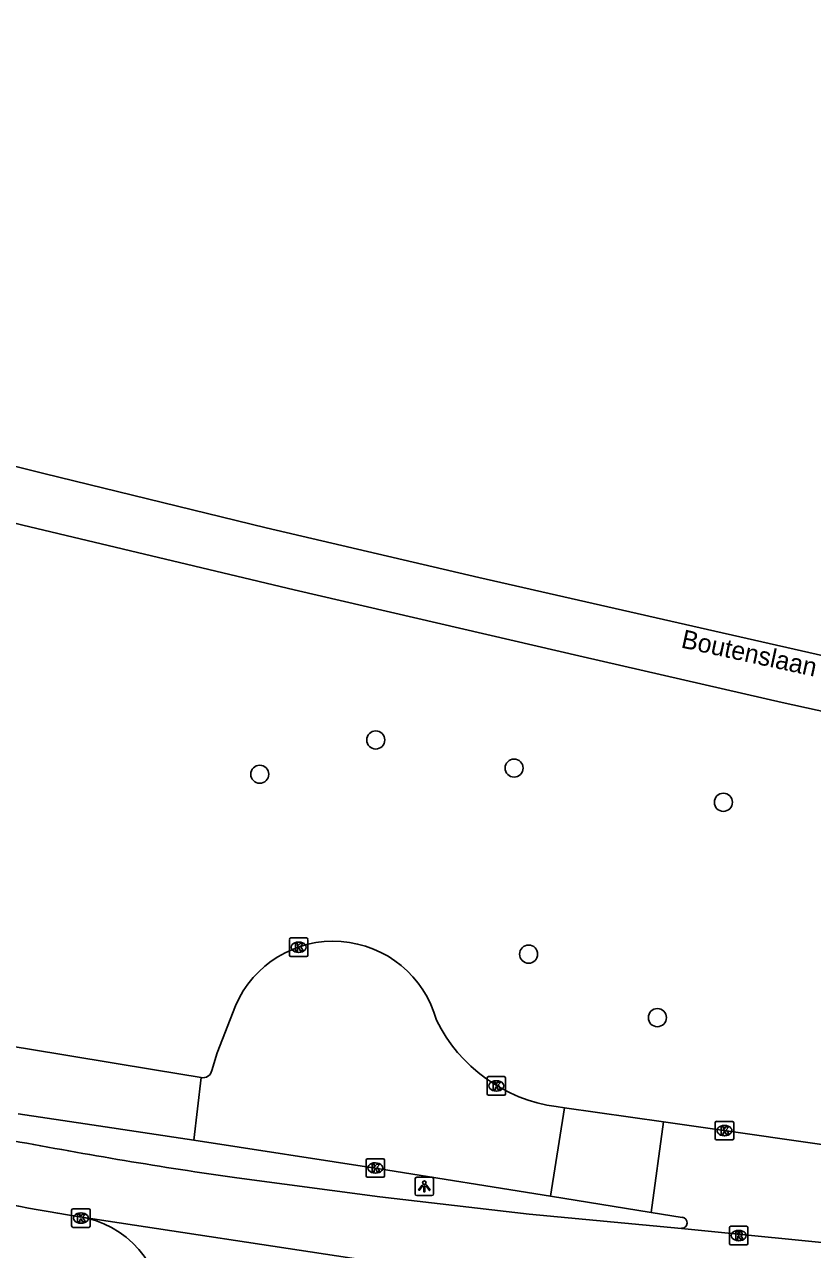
# Model space of a CAD drawing. Extents: x 160203 to 161526, y 379529 to 381797.
# Drawn here: x 161014 to 161056.6, y 381727.7 to 381793.9 of the extents above; entities that cross this region are included whole.
import ezdxf

# ---------------------------------------------------------------- set-up
doc = ezdxf.new("R2010")
doc.units = 0
for name, color, linetype in [('IMGEO_Boom', 7, 'Continuous'), ('IMGEO_Fietspad_gesloten', 7, 'Continuous'), ('IMGEO_Kolk', 7, 'Continuous'), ('IMGEO_Lichtpunt', 7, 'Continuous'), ('IMGEO_Openbare_ruimte_label', 7, 'Continuous'), ('IMGEO_Rijbaan_lokaal_gesloten', 7, 'Continuous'), ('IMGEO_Rijbaan_lokaal_open', 7, 'Continuous'), ('IMGEO_Rijbaan_regionaal_gesloten', 7, 'Continuous'), ('IMGEO_Rioolput', 7, 'Continuous')]:
    doc.layers.add(name, color=color, linetype=linetype)

msp = doc.modelspace()

# ---------------------------------------------------------------- linework, layer by layer
at = {"layer": 'IMGEO_Boom'}
for centre in [(161033.006, 381755.255), (161040.49, 381753.734), (161026.733, 381753.404), (161051.806, 381751.884), (161041.274, 381743.672), (161048.237, 381740.239)]:
    msp.add_circle(centre, 0.489, dxfattribs=at)
at = {"layer": 'IMGEO_Fietspad_gesloten'}
for points in [[(161049.533, 381728.846), (161041.308, 381729.618), (161033.225, 381730.555), (161025.491, 381731.569)], [(161016.874, 381729.484), (161017.118, 381729.447)]]:
    msp.add_lwpolyline(points, dxfattribs=at)
for centre, radius, start, end in [((161067.918, 382023.698), 295.194, 259.35423, 261.73648), ((161079.415, 382097.832), 373.62, 257.72776, 260.3637)]:
    msp.add_arc(centre, radius, start, end, dxfattribs=at)
at = {"layer": 'IMGEO_Kolk'}
for p, q in [((161028.339, 381743.622), (161028.339, 381744.474)), ((161028.414, 381744.548), (161029.266, 381744.548)), ((161028.827, 381744.328), (161028.852, 381744.328)), ((161029.34, 381744.474), (161029.34, 381743.622)), ((161029.266, 381743.548), (161028.414, 381743.548)), ((161028.85, 381743.768), (161028.825, 381743.768)), ((161039.03, 381736.123), (161039.03, 381736.975)), ((161039.105, 381737.049), (161039.957, 381737.049)), ((161040.031, 381736.975), (161040.031, 381736.123)), ((161039.541, 381736.269), (161039.516, 381736.269)), ((161039.518, 381736.829), (161039.543, 381736.829)), ((161039.957, 381736.049), (161039.105, 381736.049)), ((161051.365, 381733.706), (161051.365, 381734.558)), ((161051.44, 381734.632), (161052.292, 381734.632)), ((161051.853, 381734.412), (161051.878, 381734.412)), ((161052.366, 381734.558), (161052.366, 381733.706)), ((161052.292, 381733.632), (161051.44, 381733.632)), ((161051.876, 381733.852), (161051.851, 381733.852)), ((161032.485, 381731.683), (161032.485, 381732.535)), ((161032.56, 381732.609), (161033.412, 381732.609)), ((161032.973, 381732.389), (161032.998, 381732.389)), ((161033.486, 381732.535), (161033.486, 381731.683)), ((161033.412, 381731.609), (161032.56, 381731.609)), ((161032.996, 381731.829), (161032.971, 381731.829)), ((161016.562, 381728.974), (161016.562, 381729.826)), ((161016.637, 381729.9), (161017.489, 381729.9)), ((161017.05, 381729.68), (161017.075, 381729.68)), ((161017.563, 381729.826), (161017.563, 381728.974)), ((161017.073, 381729.12), (161017.048, 381729.12)), ((161017.489, 381728.9), (161016.637, 381728.9))]:
    msp.add_line(p, q, dxfattribs=at)
for points in [[(161028.339, 381743.622), (161028.339, 381744.474)], [(161028.414, 381744.548), (161029.266, 381744.548)], [(161028.66, 381744.248), (161028.783, 381744.248), (161028.783, 381744.097), (161028.913, 381744.248), (161029.077, 381744.248), (161028.931, 381744.097), (161029.084, 381743.848), (161028.932, 381743.848), (161028.847, 381744.012), (161028.783, 381743.945), (161028.783, 381743.848), (161028.66, 381743.848), (161028.66, 381744.248)], [(161029.34, 381744.474), (161029.34, 381743.622)], [(161029.266, 381743.548), (161028.414, 381743.548)], [(161039.03, 381736.123), (161039.03, 381736.975)], [(161039.105, 381737.049), (161039.957, 381737.049)], [(161040.031, 381736.975), (161040.031, 381736.123)], [(161039.351, 381736.749), (161039.474, 381736.749), (161039.474, 381736.598), (161039.604, 381736.749), (161039.768, 381736.749), (161039.622, 381736.598), (161039.775, 381736.349), (161039.623, 381736.349), (161039.538, 381736.513), (161039.474, 381736.446), (161039.474, 381736.349), (161039.351, 381736.349), (161039.351, 381736.749)], [(161039.957, 381736.049), (161039.105, 381736.049)], [(161051.365, 381733.706), (161051.365, 381734.558)], [(161051.44, 381734.632), (161052.292, 381734.632)], [(161051.686, 381734.332), (161051.809, 381734.332), (161051.809, 381734.181), (161051.939, 381734.332), (161052.103, 381734.332), (161051.957, 381734.181), (161052.11, 381733.932), (161051.958, 381733.932), (161051.873, 381734.096), (161051.809, 381734.029), (161051.809, 381733.932), (161051.686, 381733.932), (161051.686, 381734.332)], [(161052.366, 381734.558), (161052.366, 381733.706)], [(161052.292, 381733.632), (161051.44, 381733.632)], [(161032.485, 381731.683), (161032.485, 381732.535)], [(161032.56, 381732.609), (161033.412, 381732.609)], [(161032.806, 381732.309), (161032.929, 381732.309), (161032.929, 381732.158), (161033.059, 381732.309), (161033.223, 381732.309), (161033.077, 381732.158), (161033.23, 381731.909), (161033.078, 381731.909), (161032.993, 381732.073), (161032.929, 381732.006), (161032.929, 381731.909), (161032.806, 381731.909), (161032.806, 381732.309)], [(161033.486, 381732.535), (161033.486, 381731.683)], [(161033.412, 381731.609), (161032.56, 381731.609)], [(161016.562, 381728.974), (161016.562, 381729.826)], [(161016.637, 381729.9), (161017.489, 381729.9)], [(161016.883, 381729.6), (161017.006, 381729.6), (161017.006, 381729.449), (161017.136, 381729.6), (161017.3, 381729.6), (161017.154, 381729.449), (161017.307, 381729.2), (161017.155, 381729.2), (161017.07, 381729.364), (161017.006, 381729.297), (161017.006, 381729.2), (161016.883, 381729.2), (161016.883, 381729.6)], [(161017.563, 381729.826), (161017.563, 381728.974)], [(161017.489, 381728.9), (161016.637, 381728.9)]]:
    msp.add_lwpolyline(points, dxfattribs=at)
for centre, start, end in [((161028.416, 381744.472), 91.55205, 178.44795), ((161028.416, 381744.472), 91.55205, 178.44795), ((161029.264, 381744.472), 1.55205, 88.44795), ((161029.264, 381744.472), 1.55205, 88.44795), ((161028.416, 381743.624), 181.55205, 268.44795), ((161028.416, 381743.624), 181.55205, 268.44795), ((161029.264, 381743.624), 271.55205, 358.44795), ((161029.264, 381743.624), 271.55205, 358.44795), ((161039.107, 381736.973), 91.55205, 178.44795), ((161039.107, 381736.973), 91.55205, 178.44795), ((161039.955, 381736.973), 1.55205, 88.44795), ((161039.955, 381736.973), 1.55205, 88.44795), ((161039.107, 381736.125), 181.55205, 268.44795), ((161039.107, 381736.125), 181.55205, 268.44795), ((161039.955, 381736.125), 271.55205, 358.44795), ((161039.955, 381736.125), 271.55205, 358.44795), ((161051.442, 381734.556), 91.55205, 178.44795), ((161051.442, 381734.556), 91.55205, 178.44795), ((161052.29, 381734.556), 1.55205, 88.44795), ((161052.29, 381734.556), 1.55205, 88.44795), ((161051.442, 381733.708), 181.55205, 268.44795), ((161051.442, 381733.708), 181.55205, 268.44795), ((161052.29, 381733.708), 271.55205, 358.44795), ((161052.29, 381733.708), 271.55205, 358.44795), ((161032.562, 381732.533), 91.55205, 178.44795), ((161032.562, 381732.533), 91.55205, 178.44795), ((161033.41, 381732.533), 1.55205, 88.44795), ((161033.41, 381732.533), 1.55205, 88.44795), ((161032.562, 381731.685), 181.55205, 268.44795), ((161032.562, 381731.685), 181.55205, 268.44795), ((161033.41, 381731.685), 271.55205, 358.44795), ((161033.41, 381731.685), 271.55205, 358.44795), ((161016.639, 381729.824), 91.55205, 178.44795), ((161016.639, 381729.824), 91.55205, 178.44795), ((161017.487, 381729.824), 1.55205, 88.44795), ((161017.487, 381729.824), 1.55205, 88.44795), ((161016.639, 381728.976), 181.55205, 268.44795), ((161016.639, 381728.976), 181.55205, 268.44795), ((161017.487, 381728.976), 271.55205, 358.44795), ((161017.487, 381728.976), 271.55205, 358.44795)]:
    msp.add_arc(centre, 0.0765, start, end, dxfattribs=at)
for centre, major_axis, ratio, start_param, end_param in [((161028.826, 381744.048), (-0.387, 0.002), 0.722429, 4.712389, 7.853982), ((161028.851, 381744.048), (-0.39, 0.002), 0.717154, 1.570796, 4.712389), ((161039.517, 381736.549), (-0.387, 0.002), 0.722429, 4.712389, 7.853982), ((161039.542, 381736.549), (-0.39, 0.002), 0.717154, 1.570796, 4.712389), ((161051.852, 381734.132), (-0.387, 0.002), 0.722429, 4.712389, 7.853982), ((161051.877, 381734.132), (-0.39, 0.002), 0.717154, 1.570796, 4.712389), ((161032.972, 381732.109), (-0.387, 0.002), 0.722429, 4.712389, 7.853982), ((161032.997, 381732.109), (-0.39, 0.002), 0.717154, 1.570796, 4.712389), ((161017.049, 381729.4), (-0.387, 0.002), 0.722429, 4.712389, 7.853982), ((161017.074, 381729.4), (-0.39, 0.002), 0.717154, 1.570796, 4.712389)]:
    msp.add_ellipse(centre, major_axis=major_axis, ratio=ratio, start_param=start_param, end_param=end_param, dxfattribs=at)
at = {"layer": 'IMGEO_Lichtpunt'}
for p, q in [((161036.038, 381731.614), (161035.23, 381731.614)), ((161036.038, 381731.614), (161035.23, 381731.614)), ((161035.136, 381731.519), (161035.136, 381730.712)), ((161035.136, 381731.519), (161035.136, 381730.712)), ((161036.132, 381730.712), (161036.132, 381731.519)), ((161036.132, 381730.712), (161036.132, 381731.519)), ((161035.23, 381730.618), (161036.038, 381730.618)), ((161035.23, 381730.618), (161036.038, 381730.618))]:
    msp.add_line(p, q, dxfattribs=at)
for points in [[(161035.51, 381731.183), (161035.549, 381731.155), (161035.361, 381730.893), (161035.323, 381730.92), (161035.51, 381731.183)], [(161035.612, 381731.135), (161035.659, 381731.135), (161035.659, 381730.813), (161035.612, 381730.813), (161035.612, 381731.135)], [(161035.722, 381731.155), (161035.76, 381731.182), (161035.947, 381730.92), (161035.908, 381730.892), (161035.722, 381731.155)]]:
    msp.add_lwpolyline(points, dxfattribs=at)
msp.add_circle((161035.635, 381731.317), 0.0994, dxfattribs=at)
for centre, start, end in [((161035.23, 381731.519), 90, 180), ((161035.23, 381731.519), 90, 180), ((161036.038, 381731.519), 0, 90), ((161036.038, 381731.519), 0, 90), ((161035.23, 381730.712), 180, 270), ((161035.23, 381730.712), 180, 270), ((161036.038, 381730.712), 270, 0), ((161036.038, 381730.712), 270, 360)]:
    msp.add_arc(centre, 0.0946, start, end, dxfattribs=at)
at = {"layer": 'IMGEO_Rijbaan_lokaal_gesloten'}
for points in [[(161023.559, 381737.003), (161021.039, 381737.415), (161014.181, 381738.544)], [(161023.559, 381737.003), (161023.174, 381733.608)], [(161013.669, 381735.04), (161017.649, 381734.443), (161023.174, 381733.608)]]:
    msp.add_lwpolyline(points, dxfattribs=at)
msp.add_arc((161016.769, 381753.797), 15.471, 226.55789, 260.36896, dxfattribs=at)
at = {"layer": 'IMGEO_Rijbaan_lokaal_open'}
for points in [[(161025.415, 381740.882), (161024.433, 381738.344), (161024.144, 381737.386)], [(161043.222, 381735.362), (161042.464, 381730.58)], [(161043.222, 381735.362), (161042.771, 381735.426)], [(161048.566, 381734.6), (161043.222, 381735.362)], [(161048.566, 381734.6), (161047.902, 381729.709)], [(161078.264, 381730.297), (161071.37, 381731.349), (161048.566, 381734.6)], [(161023.174, 381733.608), (161033.209, 381732.061), (161042.464, 381730.58)], [(161042.464, 381730.58), (161047.902, 381729.709)], [(161047.902, 381729.709), (161049.578, 381729.441)], [(161017.118, 381729.447), (161032.311, 381727.142)], [(161021.402, 381725.182), (161021.297, 381725.643), (161021.152, 381726.092), (161020.967, 381726.527), (161020.744, 381726.943), (161020.485, 381727.338), (161020.191, 381727.708), (161019.866, 381728.051), (161019.511, 381728.363), (161019.13, 381728.642), (161018.725, 381728.886), (161018.3, 381729.093), (161017.859, 381729.261), (161017.404, 381729.388), (161017.118, 381729.447)], [(161049.533, 381728.846), (161059.471, 381727.846), (161077.765, 381724.676)]]:
    msp.add_lwpolyline(points, dxfattribs=at)
for centre, radius, start, end in [((161030.715, 381738.601), 5.77, 15.05296, 156.71888), ((161043.955, 381743.903), 8.559, 206.3786, 262.0494), ((161023.665, 381737.48), 0.488, 257.49667, 348.92893), ((161049.554, 381729.144), 0.298, 265.8827, 85.46718)]:
    msp.add_arc(centre, radius, start, end, dxfattribs=at)
at = {"layer": 'IMGEO_Rijbaan_regionaal_gesloten'}
for points in [[(160924.859, 381793.944), (160925.219, 381793.836), (160932.99, 381791.589), (160940.822, 381789.378), (160948.647, 381787.174), (160956.184, 381785.094), (160968.166, 381781.822), (160979.903, 381778.661), (160991.646, 381775.583), (161003.024, 381772.663), (161015.054, 381769.67), (161027.088, 381766.724), (161038.576, 381764.048), (161050.554, 381761.325), (161062.699, 381758.567), (161077.95, 381755.315)], [(160969.105, 381778.417), (160984.653, 381774.366), (160999.35, 381770.568), (161000, 381770.403), (161013.924, 381766.869), (161028.59, 381763.382), (161044.221, 381759.753), (161054.991, 381757.276), (161068.719, 381754.268), (161077.399, 381752.406)]]:
    msp.add_lwpolyline(points, dxfattribs=at)
at = {"layer": 'IMGEO_Rioolput'}
for p, q in [((161052.21, 381728.957), (161053.062, 381728.957)), ((161052.135, 381728.031), (161052.135, 381728.883)), ((161052.623, 381728.737), (161052.648, 381728.737)), ((161053.136, 381728.883), (161053.136, 381728.031)), ((161053.062, 381727.957), (161052.21, 381727.957)), ((161052.646, 381728.177), (161052.621, 381728.177))]:
    msp.add_line(p, q, dxfattribs=at)
for points in [[(161052.21, 381728.957), (161053.062, 381728.957)], [(161052.135, 381728.031), (161052.135, 381728.883)], [(161052.724, 381728.655), (161052.472, 381728.657), (161052.472, 381728.257)], [(161052.472, 381728.257), (161052.596, 381728.257), (161052.596, 381728.419), (161052.607, 381728.419)], [(161052.65, 381728.576), (161052.596, 381728.576), (161052.596, 381728.495)], [(161052.596, 381728.495), (161052.648, 381728.495)], [(161052.654, 381728.39), (161052.725, 381728.257), (161052.865, 381728.257), (161052.8, 381728.383)], [(161053.136, 381728.883), (161053.136, 381728.031)], [(161053.062, 381727.957), (161052.21, 381727.957)]]:
    msp.add_lwpolyline(points, dxfattribs=at)
for centre, radius, start, end in [((161052.212, 381728.881), 0.0765, 91.55205, 178.44795), ((161052.212, 381728.881), 0.0765, 91.55205, 178.44795), ((161053.06, 381728.881), 0.0765, 1.55205, 88.44795), ((161053.06, 381728.881), 0.0765, 1.55205, 88.44795), ((161052.606, 381728.366), 0.0533, 26.02933, 88.69889), ((161052.632, 381728.684), 0.19, 274.7715, 282.96867), ((161052.656, 381728.48), 0.0964, 77.00612, 93.18647), ((161052.67, 381728.537), 0.0378, 276.66336, 79.67722), ((161052.723, 381728.545), 0.109, 350.36119, 89.41601), ((161052.721, 381728.545), 0.112, 277.58423, 350.98172), ((161052.705, 381728.33), 0.108, 29.51342, 73.79051), ((161052.212, 381728.033), 0.0765, 181.55205, 268.44795), ((161052.212, 381728.033), 0.0765, 181.55205, 268.44795), ((161053.06, 381728.033), 0.0765, 271.55205, 358.44795), ((161053.06, 381728.033), 0.0765, 271.55205, 358.44795)]:
    msp.add_arc(centre, radius, start, end, dxfattribs=at)
for centre, major_axis, ratio, start_param, end_param in [((161052.622, 381728.457), (-0.387, 0.002), 0.722429, 4.712389, 7.853982), ((161052.647, 381728.457), (-0.39, 0.002), 0.717154, 1.570796, 4.712389)]:
    msp.add_ellipse(centre, major_axis=major_axis, ratio=ratio, start_param=start_param, end_param=end_param, dxfattribs=at)

# ---------------------------------------------------------------- texts
at = {"layer": 'IMGEO_Openbare_ruimte_label'}
msp.add_text('Boutenslaan', height=1, rotation=347.70114, dxfattribs=at).set_placement((161049.472, 381760.26))

doc.saveas('drawing.dxf')
